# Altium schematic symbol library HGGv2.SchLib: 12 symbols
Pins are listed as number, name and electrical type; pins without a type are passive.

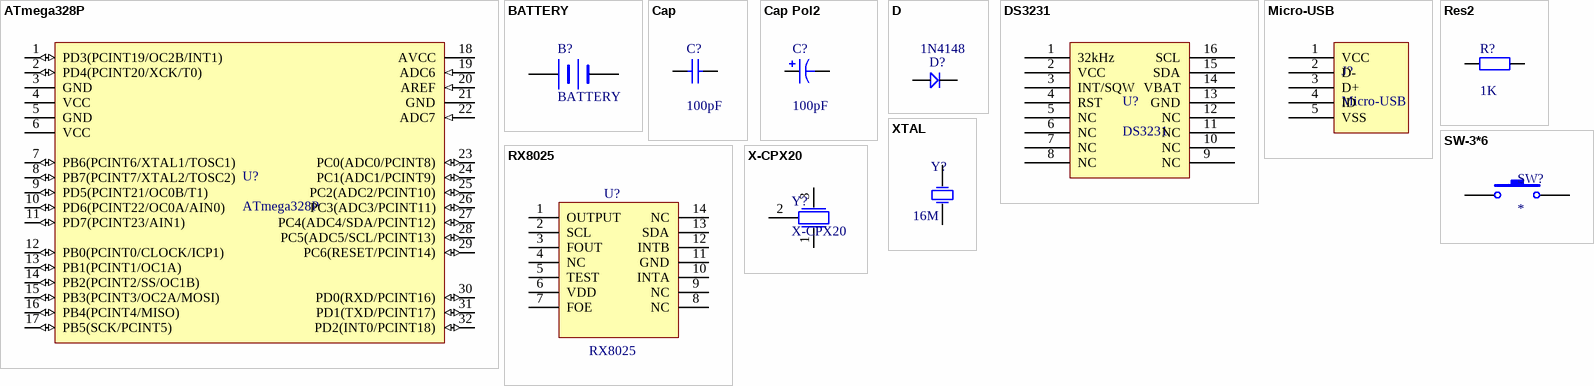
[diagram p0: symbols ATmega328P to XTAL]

## ATmega328P
designator U?
footprint LQFP32 (RS_R5F212G4)
pins: 1 PD3(PCINT19/OC2B/INT1) (io), 2 PD4(PCINT20/XCK/T0) (io), 3 GND (power), 4 VCC (power), 5 GND (power), 6 VCC (power), 7 PB6(PCINT6/XTAL1/TOSC1) (io), 8 PB7(PCINT7/XTAL2/TOSC2) (io), 9 PD5(PCINT21/OC0B/T1) (io), 10 PD6(PCINT22/OC0A/AIN0) (io), 11 PD7(PCINT23/AIN1) (io), 12 PB0(PCINT0/CLOCK/ICP1) (io), 13 PB1(PCINT1/OC1A) (io), 14 PB2(PCINT2/SS/OC1B) (io), 15 PB3(PCINT3/OC2A/MOSI) (io), 16 PB4(PCINT4/MISO) (io), 17 PB5(SCK/PCINT5) (io), 18 AVCC (power), 19 ADC6 (in), 20 AREF (in), 21 GND (power), 22 ADC7 (in), 23 PC0(ADC0/PCINT8) (io), 24 PC1(ADC1/PCINT9) (io), 25 PC2(ADC2/PCINT10) (io), 26 PC3(ADC3/PCINT11) (io), 27 PC4(ADC4/SDA/PCINT12) (io), 28 PC5(ADC5/SCL/PCINT13) (io), 29 PC6(RESET/PCINT14) (io), 30 PD0(RXD/PCINT16) (io), 31 PD1(TXD/PCINT17) (io), 32 PD2(INT0/PCINT18) (io)

## BATTERY
designator B?
footprint BT
pins: 1 +, 2 -

## Cap
designator C?, comment 100pF
Capacitor
footprint C0805 (hip Capacitor, 2-Leads, Body 2,0x1.25mm, IPC Medium Density)
pins: 1, 2

## Cap Pol2
designator C?, comment 100pF
Polarized Capacitor (Axial)
footprint ELCO Case D
pins: 1, 2
1 alternate drawing of the same symbol

## D
designator D?, comment 1N4148
footprint DIODE_3*5.3
pins: 1, 2

## DS3231
designator U?
footprint SOIC127P1050X265-16N (SOIC SMB460)
pins: 1 32kHz, 2 VCC, 3 INT/SQW, 4 RST, 5 NC, 6 NC, 7 NC, 8 NC, 9 NC, 10 NC, 11 NC, 12 NC, 13 GND, 14 VBAT, 15 SDA, 16 SCL

## Micro-USB
designator J?
footprint USB_MICRO (USB方孔)
pins: 1 VCC, 2 D- , 3 D+, 4 ID, 5 VSS

## Res2
designator R?, comment 1K
Resistor
footprint R0805 (hip Resistor, 2-Leads, Body 2,0x1.25mm, IPC Medium Density)
pins: 1, 2

## RX8025
designator U?
footprint SO-14
pins: 1 OUTPUT, 2 SCL, 3 FOUT, 4 NC, 5 TEST, 6 VDD, 7 FOE, 8 NC, 9 NC, 10 INTA, 11 GND, 12 INTB, 13 SDA, 14 NC

## SW-3*6
designator SW?
footprint 3*6
pins: 1, 2

## X-CPX20
designator Y?
footprint X-CPX20 (贴片晶振)
pins: 1, 2, 3

## XTAL
designator Y?  value 16M  (hidden comment: XTAL)
晶振
footprint X-HC49U (插件晶振)
footprint X-SM49
pins: 1 OSC1, 2 OSC2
